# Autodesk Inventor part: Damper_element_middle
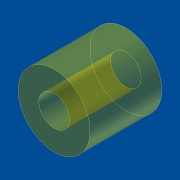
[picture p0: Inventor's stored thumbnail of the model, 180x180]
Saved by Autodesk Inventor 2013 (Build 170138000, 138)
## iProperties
Shininess: 20.0
Length Units: 11269
Angle Units: 11279
Time Units: 11290
Mass Units: 11283
Length Display Precision: 3
Angle Display Precision: 2
Created: 2001-04
Part Number: Damper_element_middle
Material: Standard
Document SubType Name: Modellieren
Designer: dl
Density: 1 g/cm^3
Density: 0.0
Volumn: 0.0
Area: 0.0
PropertySet Name: Model Information
Control State: 0
Master: False
Checked Out: False
Author: dl
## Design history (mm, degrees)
body "Solid1"
sketch "Sketch1"
  geometry: C1 r 10 at (0, 0); C2 r 4.25 at (0, 0)
  constraints: 2 centre point, 1 coincident
  dimensions: "d0" = 20 diameter of C1; "d1" = 8.5 diameter of C2
extrude "Extrusion1" new body sketch "Sketch1" distance "d2" = 20; taper "d3" = 0 deg
